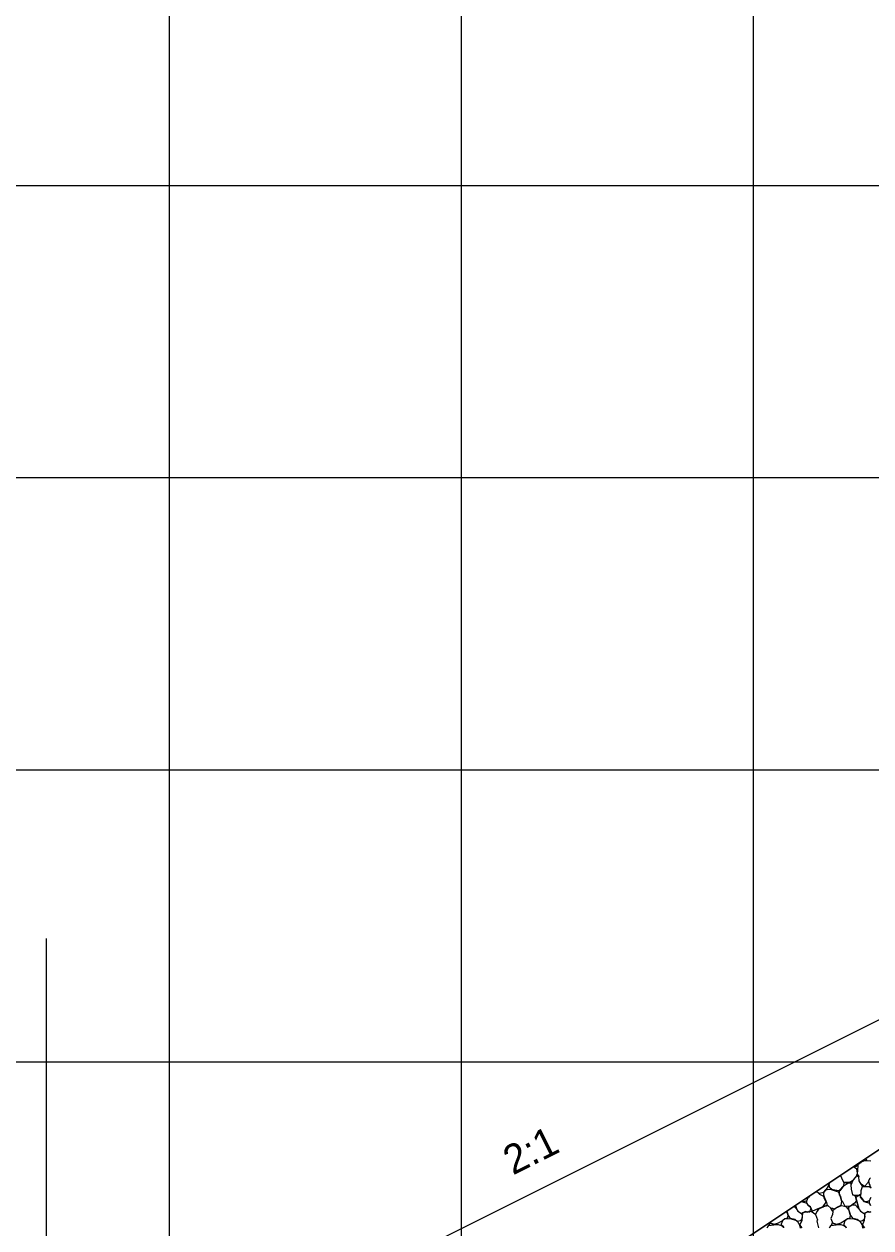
# Model space of a CAD drawing. Extents: x -26 to 2998798, y -429 to 819149.
# Drawn here: x 225.02 to 254.02, y 2527.31 to 2568.53 of the extents above; entities that cross this region are included whole.
import ezdxf

# ---------------------------------------------------------------- set-up
doc = ezdxf.new("R2010")
doc.units = 0
for name, color, linetype in [('DESIGN - EARTHWORK - Excavation Limit Lines', 7, 'Continuous'), ('DESIGN - EARTHWORK - Shapes', 7, 'Continuous'), ('DESIGN - PROFILE - Patterning', 7, 'Continuous'), ('DESIGN - SCRATCH - User 3', 7, 'Continuous'), ('DESIGN - SCRATCH - User 4', 7, 'Continuous'), ('DESIGN - SHEET - Linework', 7, 'Continuous'), ('DESIGN - TYPICAL - Finished Grade and Subgrade', 7, 'Continuous')]:
    doc.layers.add(name, color=color, linetype=linetype)

msp = doc.modelspace()

# ---------------------------------------------------------------- linework, layer by layer
at = {"layer": 'DESIGN - EARTHWORK - Excavation Limit Lines'}
msp.add_line((225.777, 2537.224), (225.777, 2484.724), dxfattribs=at)
at = {"layer": 'DESIGN - EARTHWORK - Shapes'}
msp.add_lwpolyline([(309, 2547.734), (300, 2547.914), (299.208, 2547.909), (289, 2547.848), (281.017, 2547.801), (225.777, 2510.974)], dxfattribs=at)
at = {"layer": 'DESIGN - PROFILE - Patterning'}
msp.add_line((281.017, 2547.801), (225.777, 2510.974), dxfattribs=at)
for points in [[(253.693, 2529.585), (253.669, 2529.546), (253.574, 2529.476), (253.559, 2529.266), (253.544, 2529.106), (253.409, 2528.956), (253.334, 2528.776), (253.339, 2528.641), (253.394, 2528.456), (253.469, 2528.421), (253.509, 2528.346), (253.609, 2527.976), (253.504, 2528.346), (253.564, 2528.406), (253.629, 2528.436), (253.464, 2528.426), (253.639, 2528.436), (253.679, 2528.366), (253.789, 2528.221), (253.969, 2528.161), (254.009, 2528.086), (253.969, 2528.156), (253.969, 2528.246), (254.014, 2528.356), (253.959, 2528.246), (253.874, 2528.206), (253.799, 2528.211), (253.669, 2528.371), (253.674, 2528.471), (253.629, 2528.446), (253.689, 2528.471), (253.684, 2528.596), (253.734, 2528.731), (253.824, 2528.736), (253.959, 2528.731), (254.024, 2528.691), (253.979, 2528.726), (254.004, 2528.751), (253.969, 2528.811), (253.954, 2528.926), (253.984, 2529.001), (254.009, 2529.026), (253.989, 2529.006), (253.939, 2528.916), (253.899, 2528.841), (253.804, 2528.736), (253.689, 2528.806), (253.734, 2528.736), (253.689, 2528.811), (253.624, 2528.926), (253.609, 2529.066), (253.539, 2529.086), (253.539, 2529.141), (253.579, 2529.126), (253.604, 2529.066), (253.574, 2529.126), (253.539, 2529.326), (253.422, 2529.404)], [(253.846, 2529.686), (253.879, 2529.606), (253.794, 2529.616), (253.669, 2529.556), (253.682, 2529.577)], [(254.014, 2529.601), (253.884, 2529.606), (253.848, 2529.688)], [(253.429, 2529.409), (253.499, 2529.426), (253.549, 2529.466), (253.574, 2529.461), (253.539, 2529.461), (253.499, 2529.416), (253.429, 2529.408)], [(252.142, 2528.551), (252.184, 2528.546), (252.244, 2528.501), (252.414, 2528.536), (252.539, 2528.686), (252.579, 2528.786), (252.539, 2528.686), (252.459, 2528.601), (252.399, 2528.536), (252.394, 2528.441), (252.414, 2528.381), (252.504, 2528.186), (252.524, 2528.081), (252.394, 2528.046), (252.549, 2528.081), (252.644, 2527.991), (252.714, 2527.871), (252.709, 2527.771), (252.649, 2527.636), (252.689, 2527.526), (252.684, 2527.441), (252.614, 2527.346), (252.604, 2527.316), (252.649, 2527.391), (252.834, 2527.416), (252.824, 2527.441), (252.694, 2527.491), (252.839, 2527.431), (252.904, 2527.431), (252.989, 2527.436), (253.094, 2527.401), (253.164, 2527.351), (253.169, 2527.316), (253.164, 2527.346), (253.099, 2527.406), (253.104, 2527.456), (253.139, 2527.566), (252.989, 2527.471), (252.839, 2527.431)], [(252.979, 2529.108), (253.049, 2528.951), (253.089, 2528.866), (253.079, 2528.756), (253.234, 2528.846), (253.289, 2528.871), (253.404, 2528.941), (253.274, 2528.866), (253.089, 2528.871), (253.239, 2528.846), (253.319, 2528.861), (253.329, 2528.786), (253.339, 2528.646), (253.389, 2528.451), (253.479, 2528.426), (253.504, 2528.351), (253.514, 2528.226), (253.459, 2528.161), (253.374, 2528.101), (253.304, 2528.061), (253.144, 2528.051), (253.064, 2528.211), (253.024, 2528.236), (252.989, 2528.386), (252.949, 2528.451), (252.949, 2528.536), (252.939, 2528.591), (253.084, 2528.751), (252.954, 2528.586), (252.909, 2528.581), (252.724, 2528.616), (252.679, 2528.626), (252.614, 2528.681), (252.589, 2528.796), (252.613, 2528.865)], [(251.648, 2528.222), (251.649, 2528.221), (251.829, 2528.161), (251.869, 2528.086), (251.829, 2528.156), (251.829, 2528.246), (251.874, 2528.356), (251.819, 2528.246), (251.734, 2528.206), (251.659, 2528.211), (251.65, 2528.222)], [(252.234, 2527.321), (252.184, 2527.541), (252.199, 2527.581), (252.139, 2527.766), (251.969, 2527.871), (251.889, 2527.856), (251.934, 2527.866), (251.929, 2527.891), (251.959, 2527.951), (251.974, 2527.951), (251.949, 2528.031), (251.884, 2528.086), (251.939, 2528.031), (251.984, 2527.951), (251.989, 2527.921), (252.034, 2527.896), (252.219, 2527.976), (252.394, 2528.041), (252.224, 2527.961), (252.184, 2527.891), (252.129, 2527.791), (252.184, 2527.886), (252.219, 2527.961), (252.219, 2527.981), (252.389, 2528.051), (252.489, 2528.196), (252.419, 2528.341), (252.404, 2528.391), (252.274, 2528.456), (252.234, 2528.496), (252.189, 2528.541), (252.139, 2528.548)], [(251.903, 2528.391), (251.889, 2528.356), (251.901, 2528.39)], [(252.474, 2528.616), (252.564, 2528.636), (252.664, 2528.626), (252.894, 2528.551), (252.949, 2528.466), (253.009, 2528.231), (252.994, 2528.081), (252.879, 2528.026), (252.844, 2527.996), (252.709, 2527.896), (252.644, 2527.991), (252.709, 2527.991), (252.759, 2527.971), (252.834, 2527.996), (253.009, 2528.076), (253.114, 2528.061), (253.169, 2528.041), (253.264, 2527.926), (253.314, 2527.781), (253.299, 2527.651), (253.214, 2527.621), (253.144, 2527.571), (253.204, 2527.621), (253.324, 2527.641), (253.434, 2527.626), (253.549, 2527.591), (253.634, 2527.556), (253.729, 2527.401), (253.744, 2527.311), (253.729, 2527.406), (253.799, 2527.321), (253.729, 2527.411), (253.804, 2527.576), (253.824, 2527.826), (253.914, 2527.866), (253.979, 2527.856), (254.019, 2527.876), (253.994, 2527.856), (253.919, 2527.871), (253.834, 2527.826), (253.794, 2527.811), (253.809, 2527.706), (253.789, 2527.601), (253.734, 2527.551), (253.639, 2527.536), (253.554, 2527.606), (253.409, 2527.636), (253.314, 2527.771), (253.259, 2527.941), (253.259, 2528.031), (253.379, 2528.101), (253.484, 2528.101), (253.599, 2527.981), (253.659, 2527.886), (253.784, 2527.811)], [(251.392, 2528.051), (251.459, 2527.981), (251.519, 2527.886), (251.644, 2527.811)], [(251.44, 2528.083), (251.469, 2527.976), (251.439, 2528.082)], [(250.546, 2527.487), (250.544, 2527.441), (250.474, 2527.346), (250.464, 2527.316), (250.509, 2527.391), (250.694, 2527.416), (250.684, 2527.441), (250.554, 2527.491), (250.699, 2527.431), (250.764, 2527.431), (250.849, 2527.436), (250.954, 2527.401), (251.024, 2527.351), (251.029, 2527.316), (251.024, 2527.346), (250.959, 2527.406), (250.964, 2527.456), (250.999, 2527.566), (250.849, 2527.471), (250.699, 2527.431)], [(251.139, 2527.882), (251.174, 2527.781), (251.159, 2527.651), (251.074, 2527.621), (251.004, 2527.571), (251.064, 2527.621), (251.184, 2527.641), (251.294, 2527.626), (251.409, 2527.591), (251.494, 2527.556), (251.589, 2527.401), (251.604, 2527.311), (251.589, 2527.406), (251.659, 2527.321), (251.589, 2527.411), (251.664, 2527.576), (251.684, 2527.826), (251.774, 2527.866), (251.839, 2527.856), (251.879, 2527.876), (251.854, 2527.856), (251.779, 2527.871), (251.694, 2527.826), (251.654, 2527.811), (251.669, 2527.706), (251.649, 2527.601), (251.594, 2527.551), (251.499, 2527.536), (251.414, 2527.606), (251.269, 2527.636), (251.174, 2527.771), (251.138, 2527.881)]]:
    msp.add_lwpolyline(points, dxfattribs=at)
at = {"layer": 'DESIGN - SCRATCH - User 3'}
msp.add_lwpolyline([(299.208, 2547.909), (289, 2547.848), (281.017, 2547.801), (225.777, 2510.974), (230.186, 2511.075), (242.134, 2511.654), (249.866, 2511.679), (265.88, 2511.997), (267.637, 2514.832), (268.915, 2514.926), (272.672, 2515.326), (273.716, 2515.78), (276.491, 2517.642), (280.232, 2519.336), (286.77, 2522.859), (291.559, 2525.363), (293.354, 2526.226), (296.534, 2527.058), (268.06, 2527.144)], close=True, dxfattribs=at)
at = {"layer": 'DESIGN - SCRATCH - User 4'}
msp.add_line((281.017, 2547.801), (220.5, 2517.542), dxfattribs=at)
at = {"layer": 'DESIGN - SHEET - Linework'}
for p, q in [((230, 2443), (230, 2653)), ((240, 2443), (240, 2653)), ((250, 2443), (250, 2653)), ((150, 2563), (450, 2563)), ((150, 2553), (450, 2553)), ((150, 2543), (450, 2543)), ((150, 2533), (450, 2533))]:
    msp.add_line(p, q, dxfattribs=at)
at = {"layer": 'DESIGN - TYPICAL - Finished Grade and Subgrade'}
msp.add_line((281.017, 2547.801), (225.777, 2510.974), dxfattribs=at)

# ---------------------------------------------------------------- texts
at = {"layer": 'DESIGN - SCRATCH - User 4'}
msp.add_text('2:1', height=1, rotation=26.5651, dxfattribs=at).set_placement((241.758, 2529.105))

doc.saveas('drawing.dxf')
